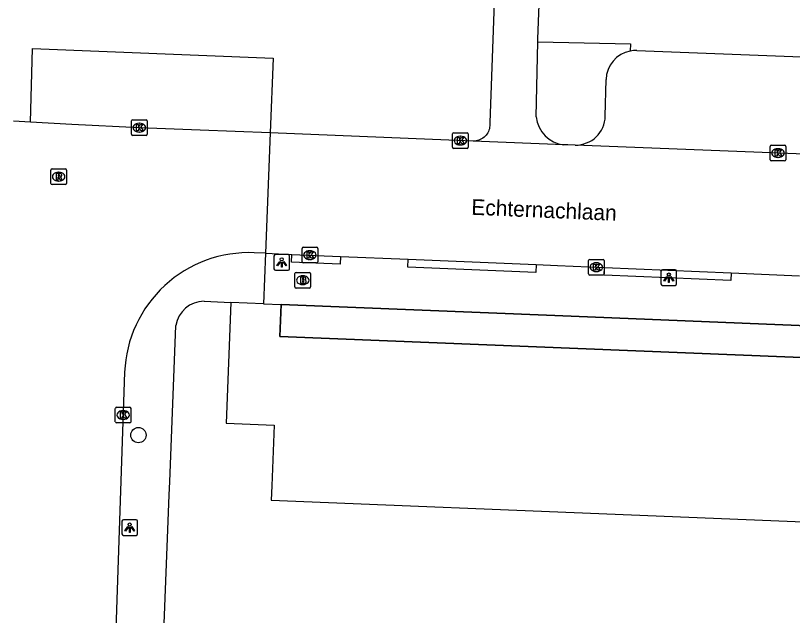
# Model space of a CAD drawing. Extents: x 160787 to 161428, y 386828 to 387483.
# Drawn here: x 160937.63 to 160987.27, y 387378.71 to 387417.03 of the extents above; entities that cross this region are included whole.
import ezdxf

# ---------------------------------------------------------------- set-up
doc = ezdxf.new("R2010")
doc.units = 0
for name, color, linetype in [('IMGEO_Boom', 7, 'Continuous'), ('IMGEO_Brandkraan', 7, 'Continuous'), ('IMGEO_Fietspad_open', 7, 'Continuous'), ('IMGEO_Kolk', 7, 'Continuous'), ('IMGEO_Lichtpunt', 7, 'Continuous'), ('IMGEO_Openbare_ruimte_label', 7, 'Continuous'), ('IMGEO_Pand', 7, 'Continuous'), ('IMGEO_Pand_overbouw', 7, 'Continuous'), ('IMGEO_Parkeervlak_open', 7, 'Continuous'), ('IMGEO_Rijbaan_lokaal_gesloten', 7, 'Continuous'), ('IMGEO_Rioolput', 7, 'Continuous'), ('IMGEO_Verkeerseiland_open', 7, 'Continuous'), ('IMGEO_Voetpad_open', 7, 'Continuous')]:
    doc.layers.add(name, color=color, linetype=linetype)

msp = doc.modelspace()

# ---------------------------------------------------------------- linework, layer by layer
at = {"layer": 'IMGEO_Boom'}
msp.add_circle((160945.481, 387390.231), 0.489, dxfattribs=at)
at = {"layer": 'IMGEO_Brandkraan'}
for p, q in [((160955.483, 387399.7), (160955.483, 387400.552)), ((160955.558, 387400.626), (160956.41, 387400.626)), ((160955.971, 387400.406), (160955.996, 387400.406)), ((160956.484, 387400.552), (160956.484, 387399.7)), ((160955.994, 387399.846), (160955.969, 387399.846)), ((160956.41, 387399.626), (160955.558, 387399.626))]:
    msp.add_line(p, q, dxfattribs=at)
for points in [[(160955.483, 387399.7), (160955.483, 387400.552)], [(160955.558, 387400.626), (160956.41, 387400.626)], [(160955.831, 387400.326), (160955.831, 387399.926), (160956.044, 387399.926)], [(160956.062, 387400.326), (160955.831, 387400.326)], [(160956.484, 387400.552), (160956.484, 387399.7)], [(160956.01, 387400.245), (160955.956, 387400.245), (160955.956, 387400.169)], [(160955.956, 387400.169), (160956.009, 387400.169)], [(160956.018, 387400.093), (160955.956, 387400.093), (160955.956, 387400.012)], [(160955.956, 387400.012), (160956.018, 387400.012)], [(160956.41, 387399.626), (160955.558, 387399.626)]]:
    msp.add_lwpolyline(points, dxfattribs=at)
for centre, radius, start, end in [((160955.56, 387400.55), 0.0765, 91.552, 178.448), ((160955.56, 387400.55), 0.0765, 91.552, 178.448), ((160956.066, 387400.181), 0.145, 59.4692, 91.5367), ((160956.091, 387400.228), 0.0922, 285.5137, 58.1501), ((160956.408, 387400.55), 0.0765, 1.552, 88.448), ((160956.408, 387400.55), 0.0765, 1.552, 88.448), ((160956.011, 387400.207), 0.0379, 267.8285, 90.9355), ((160956.019, 387400.052), 0.0404, 269.8759, 90.5077), ((160956.05, 387400.177), 0.251, 268.6676, 293.5347), ((160956.096, 387400.036), 0.105, 301.3115, 78.989), ((160955.56, 387399.702), 0.0765, 181.552, 268.448), ((160955.56, 387399.702), 0.0765, 181.552, 268.448), ((160956.408, 387399.702), 0.0765, 271.552, 358.448), ((160956.408, 387399.702), 0.0765, 271.552, 358.448)]:
    msp.add_arc(centre, radius, start, end, dxfattribs=at)
for centre, major_axis, ratio, start_param, end_param in [((160955.97, 387400.126), (-0.387, 0.002), 0.722429, 4.712389, 7.853982), ((160955.995, 387400.126), (-0.39, 0.002), 0.717154, 1.570796, 4.712389)]:
    msp.add_ellipse(centre, major_axis=major_axis, ratio=ratio, start_param=start_param, end_param=end_param, dxfattribs=at)
at = {"layer": 'IMGEO_Fietspad_open'}
for points in [[(160971, 387415.348), (160971.004, 387415.533), (160972.457, 387452.681), (160972.898, 387463.94)], [(160968.627, 387429.067), (160967.926, 387410.193), (160967.929, 387410.17), (160967.935, 387410.077), (160967.933, 387409.984), (160967.923, 387409.891), (160967.904, 387409.799), (160967.878, 387409.71), (160967.843, 387409.623), (160967.801, 387409.54), (160967.751, 387409.46), (160967.695, 387409.386), (160967.632, 387409.317), (160967.563, 387409.253), (160967.489, 387409.196), (160967.41, 387409.146), (160967.327, 387409.104), (160967.241, 387409.068), (160967.152, 387409.041), (160967.06, 387409.022), (160966.967, 387409.011), (160966.874, 387409.008)], [(160970.896, 387410.548), (160971, 387415.348)]]:
    msp.add_lwpolyline(points, dxfattribs=at)
msp.add_arc((160972.87, 387410.754), 1.985, 185.9556, 264.2061, dxfattribs=at)
at = {"layer": 'IMGEO_Kolk'}
for p, q in [((160945.043, 387409.441), (160945.043, 387410.293)), ((160945.118, 387410.367), (160945.97, 387410.367)), ((160946.044, 387410.293), (160946.044, 387409.441)), ((160945.531, 387410.147), (160945.556, 387410.147)), ((160945.97, 387409.367), (160945.118, 387409.367)), ((160945.554, 387409.587), (160945.529, 387409.587)), ((160965.555, 387408.616), (160965.555, 387409.468)), ((160965.63, 387409.542), (160966.482, 387409.542)), ((160966.043, 387409.322), (160966.068, 387409.322)), ((160966.556, 387409.468), (160966.556, 387408.616)), ((160966.066, 387408.762), (160966.041, 387408.762)), ((160985.918, 387408.745), (160986.77, 387408.745)), ((160966.482, 387408.542), (160965.63, 387408.542)), ((160985.843, 387407.819), (160985.843, 387408.671)), ((160986.331, 387408.525), (160986.356, 387408.525)), ((160986.844, 387408.671), (160986.844, 387407.819)), ((160986.77, 387407.745), (160985.918, 387407.745)), ((160986.354, 387407.965), (160986.329, 387407.965)), ((160955.936, 387401.3), (160955.936, 387402.152)), ((160956.011, 387402.226), (160956.863, 387402.226)), ((160956.424, 387402.006), (160956.449, 387402.006)), ((160956.937, 387402.152), (160956.937, 387401.3)), ((160956.447, 387401.446), (160956.422, 387401.446)), ((160974.24, 387400.531), (160974.24, 387401.383)), ((160974.315, 387401.457), (160975.167, 387401.457)), ((160975.241, 387401.383), (160975.241, 387400.531)), ((160956.863, 387401.226), (160956.011, 387401.226)), ((160974.728, 387401.237), (160974.753, 387401.237)), ((160975.167, 387400.457), (160974.315, 387400.457)), ((160974.751, 387400.677), (160974.726, 387400.677)), ((160944.007, 387391.085), (160944.007, 387391.937)), ((160944.082, 387392.011), (160944.934, 387392.011)), ((160945.008, 387391.937), (160945.008, 387391.085)), ((160944.495, 387391.791), (160944.52, 387391.791)), ((160944.934, 387391.011), (160944.082, 387391.011)), ((160944.518, 387391.231), (160944.493, 387391.231))]:
    msp.add_line(p, q, dxfattribs=at)
for points in [[(160945.043, 387409.441), (160945.043, 387410.293)], [(160945.118, 387410.367), (160945.97, 387410.367)], [(160946.044, 387410.293), (160946.044, 387409.441)], [(160945.364, 387410.067), (160945.487, 387410.067), (160945.487, 387409.916), (160945.617, 387410.067), (160945.781, 387410.067), (160945.635, 387409.916), (160945.788, 387409.667), (160945.636, 387409.667), (160945.551, 387409.831), (160945.487, 387409.764), (160945.487, 387409.667), (160945.364, 387409.667), (160945.364, 387410.067)], [(160945.97, 387409.367), (160945.118, 387409.367)], [(160965.555, 387408.616), (160965.555, 387409.468)], [(160965.63, 387409.542), (160966.482, 387409.542)], [(160965.876, 387409.242), (160965.999, 387409.242), (160965.999, 387409.091), (160966.129, 387409.242), (160966.293, 387409.242), (160966.147, 387409.091), (160966.3, 387408.842), (160966.148, 387408.842), (160966.063, 387409.006), (160965.999, 387408.939), (160965.999, 387408.842), (160965.876, 387408.842), (160965.876, 387409.242)], [(160966.556, 387409.468), (160966.556, 387408.616)], [(160985.918, 387408.745), (160986.77, 387408.745)], [(160966.482, 387408.542), (160965.63, 387408.542)], [(160985.843, 387407.819), (160985.843, 387408.671)], [(160986.164, 387408.445), (160986.287, 387408.445), (160986.287, 387408.294), (160986.417, 387408.445), (160986.581, 387408.445), (160986.435, 387408.294), (160986.588, 387408.045), (160986.436, 387408.045), (160986.351, 387408.209), (160986.287, 387408.142), (160986.287, 387408.045), (160986.164, 387408.045), (160986.164, 387408.445)], [(160986.844, 387408.671), (160986.844, 387407.819)], [(160986.77, 387407.745), (160985.918, 387407.745)], [(160955.936, 387401.3), (160955.936, 387402.152)], [(160956.011, 387402.226), (160956.863, 387402.226)], [(160956.257, 387401.926), (160956.38, 387401.926), (160956.38, 387401.775), (160956.51, 387401.926), (160956.674, 387401.926), (160956.528, 387401.775), (160956.681, 387401.526), (160956.529, 387401.526), (160956.444, 387401.69), (160956.38, 387401.623), (160956.38, 387401.526), (160956.257, 387401.526), (160956.257, 387401.926)], [(160956.937, 387402.152), (160956.937, 387401.3)], [(160974.24, 387400.531), (160974.24, 387401.383)], [(160974.315, 387401.457), (160975.167, 387401.457)], [(160975.241, 387401.383), (160975.241, 387400.531)], [(160956.863, 387401.226), (160956.011, 387401.226)], [(160974.561, 387401.157), (160974.684, 387401.157), (160974.684, 387401.006), (160974.814, 387401.157), (160974.978, 387401.157), (160974.832, 387401.006), (160974.985, 387400.757), (160974.833, 387400.757), (160974.748, 387400.921), (160974.684, 387400.854), (160974.684, 387400.757), (160974.561, 387400.757), (160974.561, 387401.157)], [(160975.167, 387400.457), (160974.315, 387400.457)], [(160944.007, 387391.085), (160944.007, 387391.937)], [(160944.082, 387392.011), (160944.934, 387392.011)], [(160945.008, 387391.937), (160945.008, 387391.085)], [(160944.328, 387391.711), (160944.451, 387391.711), (160944.451, 387391.56), (160944.581, 387391.711), (160944.745, 387391.711), (160944.599, 387391.56), (160944.752, 387391.311), (160944.6, 387391.311), (160944.515, 387391.475), (160944.451, 387391.408), (160944.451, 387391.311), (160944.328, 387391.311), (160944.328, 387391.711)], [(160944.934, 387391.011), (160944.082, 387391.011)]]:
    msp.add_lwpolyline(points, dxfattribs=at)
for centre, start, end in [((160945.12, 387410.291), 91.552, 178.448), ((160945.12, 387410.291), 91.552, 178.448), ((160945.968, 387410.291), 1.552, 88.448), ((160945.968, 387410.291), 1.552, 88.448), ((160945.12, 387409.443), 181.552, 268.448), ((160945.12, 387409.443), 181.552, 268.448), ((160945.968, 387409.443), 271.552, 358.448), ((160945.968, 387409.443), 271.552, 358.448), ((160965.632, 387409.466), 91.552, 178.448), ((160965.632, 387409.466), 91.552, 178.448), ((160966.48, 387409.466), 1.552, 88.448), ((160966.48, 387409.466), 1.552, 88.448), ((160985.92, 387408.669), 91.552, 178.448), ((160985.92, 387408.669), 91.552, 178.448), ((160986.768, 387408.669), 1.552, 88.448), ((160986.768, 387408.669), 1.552, 88.448), ((160965.632, 387408.618), 181.552, 268.448), ((160965.632, 387408.618), 181.552, 268.448), ((160966.48, 387408.618), 271.552, 358.448), ((160966.48, 387408.618), 271.552, 358.448), ((160985.92, 387407.821), 181.552, 268.448), ((160985.92, 387407.821), 181.552, 268.448), ((160986.768, 387407.821), 271.552, 358.448), ((160986.768, 387407.821), 271.552, 358.448), ((160956.013, 387402.15), 91.552, 178.448), ((160956.013, 387402.15), 91.552, 178.448), ((160956.861, 387402.15), 1.552, 88.448), ((160956.861, 387402.15), 1.552, 88.448), ((160956.013, 387401.302), 181.552, 268.448), ((160956.013, 387401.302), 181.552, 268.448), ((160956.861, 387401.302), 271.552, 358.448), ((160956.861, 387401.302), 271.552, 358.448), ((160974.317, 387401.381), 91.552, 178.448), ((160974.317, 387401.381), 91.552, 178.448), ((160975.165, 387401.381), 1.552, 88.448), ((160975.165, 387401.381), 1.552, 88.448), ((160974.317, 387400.533), 181.552, 268.448), ((160974.317, 387400.533), 181.552, 268.448), ((160975.165, 387400.533), 271.552, 358.448), ((160975.165, 387400.533), 271.552, 358.448), ((160944.084, 387391.935), 91.552, 178.448), ((160944.084, 387391.935), 91.552, 178.448), ((160944.932, 387391.935), 1.552, 88.448), ((160944.932, 387391.935), 1.552, 88.448), ((160944.084, 387391.087), 181.552, 268.448), ((160944.084, 387391.087), 181.552, 268.448), ((160944.932, 387391.087), 271.552, 358.448), ((160944.932, 387391.087), 271.552, 358.448)]:
    msp.add_arc(centre, 0.0765, start, end, dxfattribs=at)
for centre, major_axis, ratio, start_param, end_param in [((160945.53, 387409.867), (-0.387, 0.002), 0.722429, 4.712389, 7.853982), ((160945.555, 387409.867), (-0.39, 0.002), 0.717154, 1.570796, 4.712389), ((160966.042, 387409.042), (-0.387, 0.002), 0.722429, 4.712389, 7.853982), ((160966.067, 387409.042), (-0.39, 0.002), 0.717154, 1.570796, 4.712389), ((160986.33, 387408.245), (-0.387, 0.002), 0.722429, 4.712389, 7.853982), ((160986.355, 387408.245), (-0.39, 0.002), 0.717154, 1.570796, 4.712389), ((160956.423, 387401.726), (-0.387, 0.002), 0.722429, 4.712389, 7.853982), ((160956.448, 387401.726), (-0.39, 0.002), 0.717154, 1.570796, 4.712389), ((160974.727, 387400.957), (-0.387, 0.002), 0.722429, 4.712389, 7.853982), ((160974.752, 387400.957), (-0.39, 0.002), 0.717154, 1.570796, 4.712389), ((160944.494, 387391.511), (-0.387, 0.002), 0.722429, 4.712389, 7.853982), ((160944.519, 387391.511), (-0.39, 0.002), 0.717154, 1.570796, 4.712389)]:
    msp.add_ellipse(centre, major_axis=major_axis, ratio=ratio, start_param=start_param, end_param=end_param, dxfattribs=at)
at = {"layer": 'IMGEO_Lichtpunt'}
for p, q in [((160954.14, 387401.665), (160954.14, 387400.858)), ((160954.14, 387401.665), (160954.14, 387400.858)), ((160955.042, 387401.76), (160954.234, 387401.76)), ((160955.042, 387401.76), (160954.234, 387401.76)), ((160955.136, 387400.858), (160955.136, 387401.665)), ((160955.136, 387400.858), (160955.136, 387401.665)), ((160954.234, 387400.764), (160955.042, 387400.764)), ((160954.234, 387400.764), (160955.042, 387400.764)), ((160978.87, 387400.694), (160978.87, 387399.887)), ((160978.87, 387400.694), (160978.87, 387399.887)), ((160979.772, 387400.789), (160978.964, 387400.789)), ((160979.772, 387400.789), (160978.964, 387400.789)), ((160979.866, 387399.887), (160979.866, 387400.694)), ((160979.866, 387399.887), (160979.866, 387400.694)), ((160978.964, 387399.793), (160979.772, 387399.793)), ((160978.964, 387399.793), (160979.772, 387399.793)), ((160944.428, 387384.727), (160944.428, 387383.92)), ((160944.428, 387384.727), (160944.428, 387383.92)), ((160945.33, 387384.822), (160944.522, 387384.822)), ((160945.33, 387384.822), (160944.522, 387384.822)), ((160945.424, 387383.92), (160945.424, 387384.727)), ((160945.424, 387383.92), (160945.424, 387384.727)), ((160944.522, 387383.826), (160945.33, 387383.826)), ((160944.522, 387383.826), (160945.33, 387383.826))]:
    msp.add_line(p, q, dxfattribs=at)
for points in [[(160954.514, 387401.329), (160954.553, 387401.301), (160954.365, 387401.039), (160954.327, 387401.066), (160954.514, 387401.329)], [(160954.726, 387401.301), (160954.764, 387401.328), (160954.951, 387401.066), (160954.912, 387401.038), (160954.726, 387401.301)], [(160954.616, 387401.281), (160954.663, 387401.281), (160954.663, 387400.959), (160954.616, 387400.959), (160954.616, 387401.281)], [(160979.244, 387400.358), (160979.283, 387400.33), (160979.095, 387400.068), (160979.057, 387400.095), (160979.244, 387400.358)], [(160979.346, 387400.31), (160979.393, 387400.31), (160979.393, 387399.988), (160979.346, 387399.988), (160979.346, 387400.31)], [(160979.456, 387400.33), (160979.494, 387400.357), (160979.681, 387400.095), (160979.642, 387400.067), (160979.456, 387400.33)], [(160944.802, 387384.391), (160944.841, 387384.363), (160944.653, 387384.101), (160944.615, 387384.128), (160944.802, 387384.391)], [(160944.904, 387384.343), (160944.951, 387384.343), (160944.951, 387384.021), (160944.904, 387384.021), (160944.904, 387384.343)], [(160945.014, 387384.363), (160945.052, 387384.39), (160945.239, 387384.128), (160945.2, 387384.1), (160945.014, 387384.363)]]:
    msp.add_lwpolyline(points, dxfattribs=at)
for centre in [(160954.639, 387401.463), (160979.369, 387400.492), (160944.927, 387384.525)]:
    msp.add_circle(centre, 0.0994, dxfattribs=at)
for centre, start, end in [((160954.234, 387401.665), 90, 180), ((160954.234, 387401.665), 90, 180), ((160955.042, 387401.665), 0, 90), ((160955.042, 387401.665), 0, 90), ((160954.234, 387400.858), 180, 270), ((160954.234, 387400.858), 180, 270), ((160955.042, 387400.858), 270, 0), ((160955.042, 387400.858), 270, 360), ((160978.964, 387400.694), 90, 180), ((160978.964, 387400.694), 90, 180), ((160979.772, 387400.694), 0, 90), ((160979.772, 387400.694), 0, 90), ((160978.964, 387399.887), 180, 270), ((160978.964, 387399.887), 180, 270), ((160979.772, 387399.887), 270, 0), ((160979.772, 387399.887), 270, 360), ((160944.522, 387384.727), 90, 180), ((160944.522, 387384.727), 90, 180), ((160945.33, 387384.727), 0, 90), ((160945.33, 387384.727), 0, 90), ((160944.522, 387383.92), 180, 270), ((160944.522, 387383.92), 180, 270), ((160945.33, 387383.92), 270, 0), ((160945.33, 387383.92), 270, 360)]:
    msp.add_arc(centre, 0.0946, start, end, dxfattribs=at)
at = {"layer": 'IMGEO_Pand'}
for points in [[(160951.39, 387398.707), (160951.078, 387390.993), (160954.161, 387390.868), (160954.004, 387386.995), (160953.967, 387386.068), (161000, 387384.208), (161003.256, 387384.076), (161003.316, 387385.543), (161006.916, 387385.397), (161009.613, 387385.288), (161009.553, 387383.815), (161121.957, 387379.27), (161122.153, 387384.11), (161125.279, 387383.984), (161125.586, 387391.596)], [(160953.468, 387398.623), (160951.39, 387398.707)], [(160953.468, 387398.623), (160954.599, 387398.577)], [(161122.445, 387391.723), (161122.365, 387389.747), (161000, 387394.694), (160954.516, 387396.533), (160954.599, 387398.577)]]:
    msp.add_lwpolyline(points, dxfattribs=at)
at = {"layer": 'IMGEO_Pand_overbouw'}
msp.add_lwpolyline([(161122.445, 387391.723), (161010.336, 387396.301), (161004.35, 387396.545), (160972.089, 387397.863), (160954.599, 387398.577), (160954.516, 387396.533), (161000, 387394.694), (161122.365, 387389.747)], close=True, dxfattribs=at)
at = {"layer": 'IMGEO_Parkeervlak_open'}
for points in [[(160977.337, 387414.792), (161000, 387413.923), (161010.441, 387413.493)], [(160975.313, 387410.61), (160975.364, 387412.934)]]:
    msp.add_lwpolyline(points, dxfattribs=at)
for centre, radius, start, end in [((160977.264, 387412.894), 1.901, 100.7081, 178.7799), ((160977.267, 387412.812), 1.982, 87.9749, 100.3493), ((160973.413, 387410.651), 1.9, 269.0631, 358.7602)]:
    msp.add_arc(centre, radius, start, end, dxfattribs=at)
at = {"layer": 'IMGEO_Rijbaan_lokaal_gesloten'}
for points in [[(160938.594, 387410.21), (160937.508, 387410.272)], [(160953.91, 387409.529), (160949.428, 387409.709), (160945.547, 387409.865), (160941.231, 387410.06), (160938.594, 387410.21)], [(160953.91, 387409.529), (160953.599, 387401.847)], [(160966.874, 387409.008), (160953.91, 387409.529)], [(160972.67, 387408.779), (160966.874, 387409.008)], [(160973.382, 387408.751), (160972.917, 387408.769), (160972.67, 387408.779)], [(161011.234, 387407.252), (161000, 387407.71), (160973.382, 387408.751)], [(160953.599, 387401.847), (160952.88, 387401.877)], [(160953.599, 387401.847), (160955.286, 387401.776)], [(160955.286, 387401.776), (160958.39, 387401.645)], [(160958.39, 387401.645), (160962.715, 387401.464)], [(160962.715, 387401.464), (160970.897, 387401.12)], [(160970.897, 387401.12), (160972.26, 387401.063), (160975.261, 387400.937)], [(160975.261, 387400.937), (160983.357, 387400.596)], [(160983.357, 387400.596), (160987.72, 387400.413)], [(160944.602, 387394.259), (160943.99, 387376.56), (160943.428, 387361.764)]]:
    msp.add_lwpolyline(points, dxfattribs=at)
msp.add_arc((160952.547, 387393.932), 7.952, 87.6003, 177.6446, dxfattribs=at)
at = {"layer": 'IMGEO_Rioolput'}
for p, q in [((160939.886, 387406.31), (160939.886, 387407.162)), ((160939.961, 387407.236), (160940.813, 387407.236)), ((160940.374, 387407.016), (160940.399, 387407.016)), ((160940.887, 387407.162), (160940.887, 387406.31)), ((160940.397, 387406.456), (160940.372, 387406.456)), ((160940.813, 387406.236), (160939.961, 387406.236))]:
    msp.add_line(p, q, dxfattribs=at)
for points in [[(160939.886, 387406.31), (160939.886, 387407.162)], [(160939.961, 387407.236), (160940.813, 387407.236)], [(160940.475, 387406.934), (160940.223, 387406.936), (160940.223, 387406.536)], [(160940.401, 387406.855), (160940.347, 387406.855), (160940.347, 387406.774)], [(160940.347, 387406.774), (160940.399, 387406.774)], [(160940.887, 387407.162), (160940.887, 387406.31)], [(160940.223, 387406.536), (160940.347, 387406.536), (160940.347, 387406.698), (160940.358, 387406.698)], [(160940.405, 387406.669), (160940.476, 387406.536), (160940.616, 387406.536), (160940.551, 387406.662)], [(160940.813, 387406.236), (160939.961, 387406.236)]]:
    msp.add_lwpolyline(points, dxfattribs=at)
for centre, radius, start, end in [((160939.963, 387407.16), 0.0765, 91.552, 178.448), ((160939.963, 387407.16), 0.0765, 91.552, 178.448), ((160940.383, 387406.963), 0.19, 274.7715, 282.9687), ((160940.407, 387406.759), 0.0964, 77.0061, 93.1865), ((160940.421, 387406.816), 0.0378, 276.6634, 79.6772), ((160940.474, 387406.824), 0.109, 350.3612, 89.416), ((160940.472, 387406.824), 0.112, 277.5842, 350.9817), ((160940.811, 387407.16), 0.0765, 1.552, 88.448), ((160940.811, 387407.16), 0.0765, 1.552, 88.448), ((160939.963, 387406.312), 0.0765, 181.552, 268.448), ((160939.963, 387406.312), 0.0765, 181.552, 268.448), ((160940.357, 387406.645), 0.0533, 26.0293, 88.6989), ((160940.456, 387406.609), 0.108, 29.5134, 73.7905), ((160940.811, 387406.312), 0.0765, 271.552, 358.448), ((160940.811, 387406.312), 0.0765, 271.552, 358.448)]:
    msp.add_arc(centre, radius, start, end, dxfattribs=at)
for centre, major_axis, ratio, start_param, end_param in [((160940.373, 387406.736), (-0.387, 0.002), 0.722429, 4.712389, 7.853982), ((160940.398, 387406.736), (-0.39, 0.002), 0.717154, 1.570796, 4.712389)]:
    msp.add_ellipse(centre, major_axis=major_axis, ratio=ratio, start_param=start_param, end_param=end_param, dxfattribs=at)
at = {"layer": 'IMGEO_Verkeerseiland_open'}
msp.add_lwpolyline([(160971, 387415.348), (160976.912, 387415.22), (160976.911, 387414.761)], dxfattribs=at)
at = {"layer": 'IMGEO_Voetpad_open'}
for points in [[(160938.594, 387410.21), (160938.72, 387414.92), (160954.085, 387414.297), (160953.91, 387409.529)], [(160953.599, 387401.847), (160953.468, 387398.623)], [(160958.39, 387401.645), (160958.367, 387401.146), (160955.263, 387401.277), (160955.286, 387401.776)], [(160970.897, 387401.12), (160970.873, 387400.621), (160962.691, 387400.965), (160962.715, 387401.464)], [(160983.357, 387400.596), (160983.333, 387400.097), (160975.237, 387400.438), (160975.261, 387400.937)], [(160949.682, 387398.78), (160951.39, 387398.707)], [(160954.599, 387398.577), (160972.089, 387397.863), (161004.35, 387396.545)], [(160946.79, 387369.457), (160947.388, 387384.727), (160947.455, 387386.425), (160947.487, 387387.258), (160947.878, 387397.23)]]:
    msp.add_lwpolyline(points, dxfattribs=at)
msp.add_arc((160949.694, 387396.941), 1.839, 90.3887, 170.9498, dxfattribs=at)

# ---------------------------------------------------------------- texts
at = {"layer": 'IMGEO_Openbare_ruimte_label'}
msp.add_text('Echternachlaan', height=1, rotation=357.5926, dxfattribs=at).set_placement((160966.737, 387404.307))

doc.saveas('drawing.dxf')
